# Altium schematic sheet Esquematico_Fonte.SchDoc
size A4
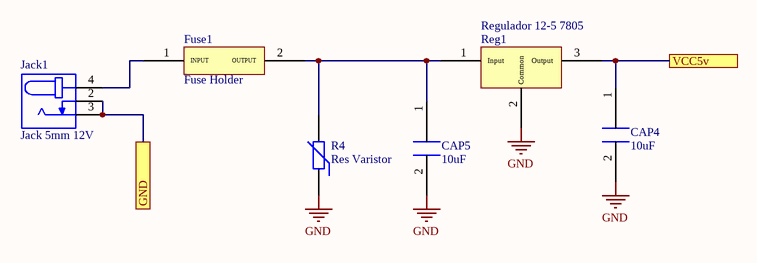
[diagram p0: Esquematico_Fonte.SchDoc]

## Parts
CAP4  10uF  [Capacitor Eletro]
CAP5  10uF  [Capacitor Eletro]
Fuse1  Fuse Holder  [Fuse Holder]
Jack1  Jack 5mm 12V  [Jack 5mm]
R4  Res Varistor  [6-0805_N]
Reg1  Regulador 12-5 7805  [Regulador 12-5 7805]

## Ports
GND, VCC5v

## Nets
GND: CAP4.2 CAP5.2 R4.1 Reg1.2(Common)
GND: Jack1.2 Jack1.3 ; port GND  [a separate net that carries the same name]
VCC5v: CAP4.1 Reg1.3(Output) ; port VCC5v
NetCAP5_1: CAP5.1 Fuse1.2(OUTPUT) R4.2 Reg1.1(Input)
NetFuse1_1: Fuse1.1(INPUT) Jack1.4

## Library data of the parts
CAP4 CAP5 = 33pF: Condensador
R4 = Res Varistor: Varistor (Voltage-Sensitive Resistor)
